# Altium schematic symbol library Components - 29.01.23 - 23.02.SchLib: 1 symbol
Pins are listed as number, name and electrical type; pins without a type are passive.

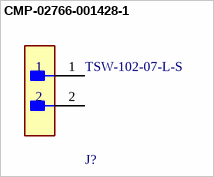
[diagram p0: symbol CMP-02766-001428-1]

## CMP-02766-001428-1
designator J?, comment TSW-102-07-L-S
CONN HEADER VERT 2POS 2.54MM; Voltage Rating: 550V; Current Rating: 7.6A; Gender: Male; Number of Contacts: 2; Connector Type: Male Pin
footprint FP-TSW-102-07-L-S-MFG
pins: 1, 2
